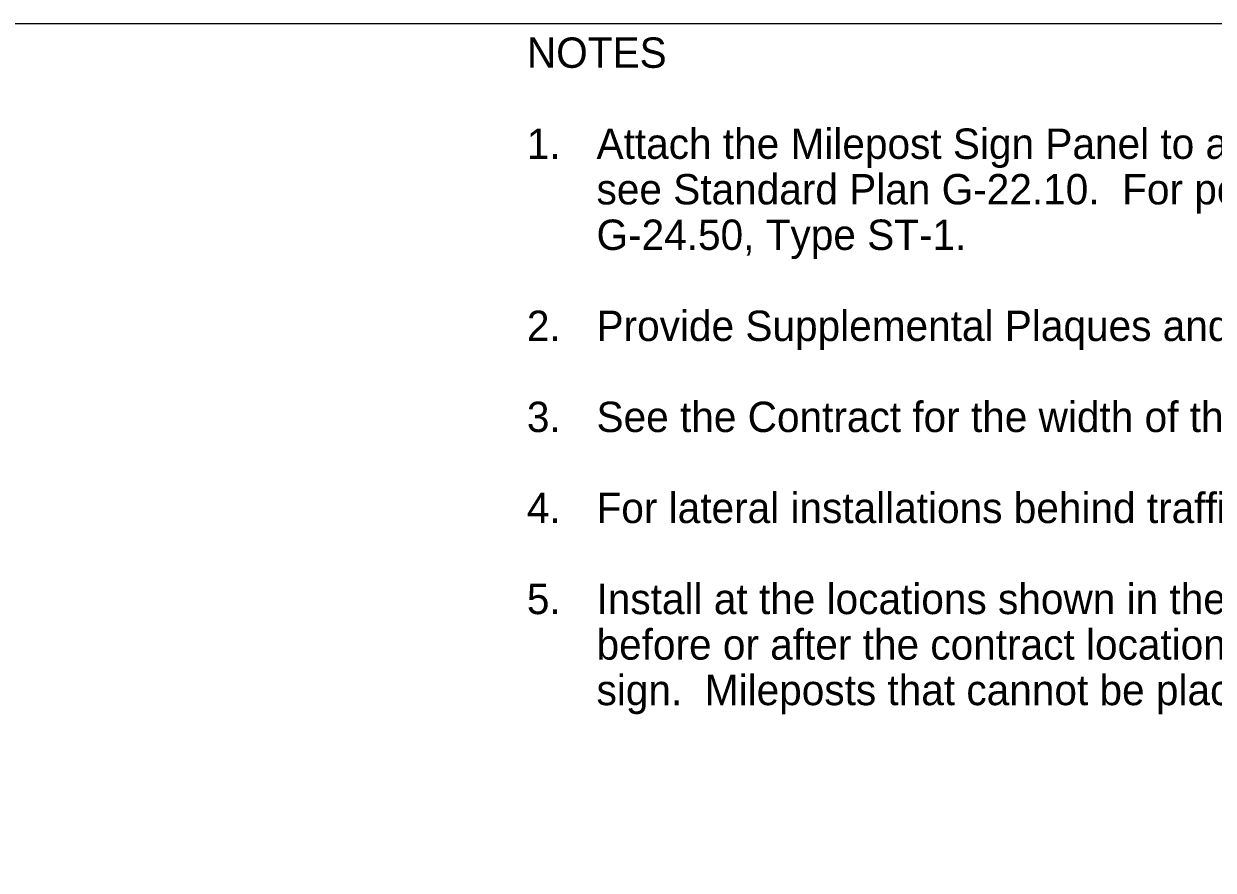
# Model space of a CAD drawing. Extents: x 99862 to 103151, y 100000 to 102076.
# Drawn here: x 101503 to 102287, y 101518 to 102076 of the extents above; entities that cross this region are included whole.
import ezdxf

# ---------------------------------------------------------------- set-up
doc = ezdxf.new("R2010")
doc.units = 0
doc.layers.add('Level 1', color=7, linetype='Continuous')
doc.layers.add('Level 20', color=7, linetype='Continuous')

msp = doc.modelspace()

# ---------------------------------------------------------------- linework, layer by layer
at = {"layer": 'Level 1'}
msp.add_lwpolyline([(99862, 99999.5), (103151, 99999.5), (103151, 102075.5), (99862, 102075.5)], close=True, dxfattribs=at)

# ---------------------------------------------------------------- texts
at = {"layer": 'Level 20'}
for s, p in [('NOTES', (101835.09, 102046.49)), ('1.', (101835.09, 101986.49)), ('Attach the Milepost Sign Panel to a timber sign post using two 3/8" diameter lag bolts, with washers;', (101881, 101986.49)), ('see Standard Plan G-22.10.  For post and attachment details on steel sign posts, see Standard Plan', (101881, 101956.49)), ('G-24.50, Type ST-1.', (101881, 101926.49)), ('2.', (101835.09, 101866.49)), ('Provide Supplemental Plaques and install on Mileposts where indicated in the Contract.', (101881, 101866.49)), ('3.', (101835.09, 101806.49)), ('See the Contract for the width of the Single-Faced Milepost Signs required (10" or 12"). ', (101881, 101806.49)), ('4.', (101835.09, 101746.49)), ('For lateral installations behind traffic barrier, 6" high curbs, and ditches, see Standard Plan G-20.10.', (101881, 101746.49)), ('5.', (101835.09, 101686.49)), ('Install at the locations shown in the Contract.  Installation may be moved 50 feet or less (longitudinally)', (101881, 101686.49)), ('before or after the contract location if obstructions are encountered, or to utilize the post of another', (101881, 101656.49)), ('sign.  Mileposts that cannot be placed within this degree of accuracy shall be omitted entirely.', (101881, 101626.49))]:
    msp.add_text(s, height=20, dxfattribs=at).set_placement(p)

doc.saveas('drawing.dxf')
